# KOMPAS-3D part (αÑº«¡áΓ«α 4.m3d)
File: created 29.01.2016 13:47:21, last saved 27.07.2016 14:57:21.
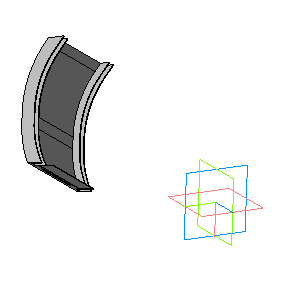
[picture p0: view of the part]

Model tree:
1. Эскиз:1
2. Операция выдавливания:1
     Толщина стенки 1 = 2; Толщина стенки 2 = 8; Расстояние 1 = 1
3. Эскиз:2
4. Операция выдавливания:2
     Толщина стенки 1 = 2; Толщина стенки 2 = 8; Расстояние 1 = 5
5. Эскиз:3
6. Операция выдавливания:3
     Толщина стенки 1 = 2; Толщина стенки 2 = 8; Расстояние 1 = 1
7. Эскиз:4
8. Операция выдавливания:4
     Толщина стенки 1 = 2; Толщина стенки 2 = 2.5; Расстояние 1 = 50
9. Эскиз:5
10. Вырезать элемент выдавливания:1
     Толщина стенки 2 = 1.2; Расстояние 1 = 40
11. Эскиз:6
12. Операция выдавливания:5
     Толщина стенки 1 = 2; Толщина стенки 2 = 2.5; Расстояние 1 = 10
13. Эскиз:7
14. Операция выдавливания:6
     Толщина стенки 1 = 2; Толщина стенки 2 = 8; Расстояние 1 = 1
15. Эскиз:8
16. Операция выдавливания:7
     Толщина стенки 1 = 2; Толщина стенки 2 = 8; Расстояние 1 = 5
17. Эскиз:9
18. Операция выдавливания:8
     Толщина стенки 1 = 2; Толщина стенки 2 = 8; Расстояние 1 = 1
19. Эскиз:10
20. Вырезать элемент выдавливания:2
     Толщина стенки 2 = 1.2; Расстояние 1 = 23
21. Эскиз:11
22. Вырезать элемент выдавливания:3
     Толщина стенки 2 = 1.2; Расстояние 1 = 1
23. Эскиз:12
24. Вырезать элемент выдавливания:4
     Расстояние 1 = 100
25. Эскиз:13
26. Операция выдавливания:9
     Расстояние 1 = 10; Расстояние 2 = 0.4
